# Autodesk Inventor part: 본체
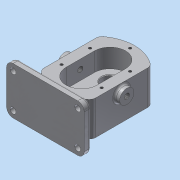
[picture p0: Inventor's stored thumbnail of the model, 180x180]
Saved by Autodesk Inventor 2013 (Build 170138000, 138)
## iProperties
Created: 2019-03
Part Number: 본체
Material: 알루미늄 6061
Document SubType Name: Modeling
Designer: dgall
Density: 2.71 g/cm^3
Mass: 1193.29 g
Surface Area: 723.767 cm^2
Volume: 440.327 cm^3
Author: dgall
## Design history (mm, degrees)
sketch "스케치2"
  geometry: L1 (-40, 44.721)-(-40, -44.721); L2 (40, 44.721)-(40, -44.721); A1 r 60 centre (0, 0) between (40, 44.721) and (-40, 44.721); A2 r 60 centre (0, 0) between (-40, -44.721) and (40, -44.721); 1 further point
  constraints: 4 end point, 4 point on circle, 2 centre point, 2 coincident, 1 horizontal alignment, 1 parallel, 1 vertical
  dimensions: "d7" = 60 radius of A1; "d8" = 60 radius of A2; "d9" = 80 distance between parallel lines of L2 L1
extrude "돌출2" new body sketch "스케치2" stored distance "d10" = 53; taper "d11" = 0 deg
sketch "스케치3"
  geometry: L1 (-24, 22)-(-24, -22); L2 (24, 22)-(24, -22); A1 r 60 centre (0, 0) between (40, 44.721) and (-40, 44.721) reference; A2 r 24 centre (0, 22) between (24, 22) and (-24, 22); A3 r 24 centre (0, -22) between (-24, -22) and (24, -22); 1 further point
  constraints: 4 end point, 4 point on circle, 4 tangent, 2 centre point, 2 vertical alignment, 1 equal radius, 1 horizontal alignment, 1 midpoint
  dimensions: "d13" = 44 distance of A3.centre A2.centre; "d14" = 24 radius of A2
extrude "돌출3" cut sketch "스케치3" distance "d15" = 29; taper "d16" = 0 deg
sketch "스케치4"
  geometry: A1 r 24 centre (0, 22) between (24, 22) and (-24, 22) reference; 2 further points
  constraints: 1 coincident
hole "구멍1" sketch "스케치4" at (0, 22) diameter "d17" = 17; stored, may be unused: countersink angle "d21" = 90 deg, drill point angle "d23" = 118 deg; dims "d18" = 6, "d19" = 25, "d20" = 15, "d22" = 8
sketch "스케치5"
  geometry: C1 r 12.5 at (0, -22); A1 r 24 centre (0, -22) between (-24, -22) and (24, -22) reference; 1 further point
  constraints: 1 centre point, 1 coincident
  dimensions: "d24" = 25 diameter of C1
extrude "돌출4" cut sketch "스케치5" distance "d25" = 15; taper "d26" = 0 deg
sketch "스케치6"
  geometry: C1 r 8.5 at (0, 22) reference; C2 r 19 at (0, 22)
  constraints: 1 centre point, 1 coincident
  dimensions: "d27" = 38 diameter of C2
extrude "돌출5" join sketch "스케치6" distance "d28" = 17; taper "d29" = 0 deg
sketch "스케치9"
  geometry: L1 (0, 0)-(0, 89.443) reference; L2 (70, 47.721)-(70, 85.721) reference; C1 r 11 at (14, 44.721); 2 further points
  constraints: 1 centre point, 1 midpoint
  dimensions: "d36" = 22 diameter of C1; "d37" = 22 vertical distance of point (70, 66.721) C1.centre; "d38" = 14 distance from line of L1 C1.centre
extrude "돌출6" join sketch "스케치9" distance "d39" = 8; taper "d40" = 0 deg
hole "구멍2" diameter "d43" = 8.376; stored, may be unused: countersink angle "d47" = 90 deg, drill point angle "d49" = 118 deg; dims "d41" = 10, "d42" = 10, "d44" = 6, "d45" = 25, "d46" = 15, "d48" = 8
node "작업 평면1"
sketch "스케치10"
  geometry: L1 (60, 46.5)-(-60, 46.5); L2 (-60, 46.5)-(-60, -26.5); L3 (-60, -26.5)-(60, -26.5); L4 (60, -26.5)-(60, 46.5); L5 (-19, -43.5)-(19, -43.5) reference; 2 further points
  constraints: 8 end point, 2 parallel, 1 horizontal, 1 midpoint, 1 perpendicular, 1 vertical alignment
  dimensions: "d51" = 73 distance of L3.end L1.start; "d53" = 120 distance of L2.end L3.end; "d54" = 90 distance between parallel lines of L5 L1
extrude "돌출7" join sketch "스케치10" distance "d55" = 10; taper "d56" = 0 deg
fillet "모깎기3" dims "d60" = 10
sketch "스케치12"
  geometry: L1 (50, 26.5)-(-50, 26.5) reference; L2 (60, 16.5)-(60, -36.5) reference; L3 (50, -46.5)-(-50, -46.5) reference; L4 (-60, -36.5)-(-60, 16.5) reference; L5 (-50, 26.5)-(50, 26.5) reference; L6 (60, 16.5)-(60, -36.5) reference; L7 (50, -46.5)-(-50, -46.5) reference; L8 (-60, -36.5)-(-60, 16.5) reference; L9 (-50, 26.5)-(50, 26.5) reference; L10 (60, 16.5)-(60, -36.5) reference; L11 (50, -46.5)-(-50, -46.5) reference; L12 (-60, -36.5)-(-60, 16.5) reference; L13 (-50, 26.5)-(50, 26.5) reference; L14 (-6, 26.5)-(-6, -16.5); L15 (-6, -16.5)-(6, -16.5); L16 (6, -16.5)-(6, 26.5); A1 r 10 centre (50, 16.5) between (60, 16.5) and (50, 26.5) reference; A2 r 10 centre (50, -36.5) between (50, -46.5) and (60, -36.5) reference; A3 r 10 centre (-50, -36.5) between (-60, -36.5) and (-50, -46.5) reference; A4 r 10 centre (-50, 16.5) between (-50, 26.5) and (-60, 16.5) reference; A5 r 10 centre (50, 16.5) between (60, 16.5) and (50, 26.5) reference; A6 r 10 centre (50, -36.5) between (50, -46.5) and (60, -36.5) reference; A7 r 10 centre (-50, -36.5) between (-60, -36.5) and (-50, -46.5) reference; A8 r 10 centre (-50, 16.5) between (-50, 26.5) and (-60, 16.5) reference; A9 r 10 centre (50, 16.5) between (60, 16.5) and (50, 26.5) reference; A10 r 10 centre (50, -36.5) between (50, -46.5) and (60, -36.5) reference; A11 r 10 centre (-50, -36.5) between (-60, -36.5) and (-50, -46.5) reference; A12 r 10 centre (-50, 16.5) between (-50, 26.5) and (-60, 16.5) reference; 3 further points
  constraints: 6 end point, 2 midpoint, 2 perpendicular, 2 point on line, 1 parallel, 1 vertical alignment
  dimensions: "d61" = 12 distance of L14.end L15.end; "d63" = 43 distance of L15.end L16.end
extrude "돌출9" join sketch "스케치12" stored distance "d64" = 12; taper "d65" = 0 deg
fillet "모깎기10" dims "d72" = 3
fillet "모깎기11" dims "d73" = 3
fillet "모깎기12" dims "d74" = 3
fillet "모깎기13" dims "d75" = 3
fillet "모깎기14" dims "d76" = 3
hole "구멍3" diameter "d79" = 9; stored, may be unused: countersink angle "d83" = 90 deg, drill point angle "d85" = 118 deg; dims "d77" = 10, "d78" = 10, "d80" = 6, "d81" = 25, "d82" = 15, "d84" = 8
sketch "스케치15"
  geometry: A1 r 24 centre (0, -22) between (-24, -22) and (24, -22) reference; A2 r 24 centre (0, 22) between (24, 22) and (-24, 22) reference; A3 r 60 centre (0, 0) between (40, 44.721) and (-40, 44.721) reference; 6 further points
  constraints: 4 horizontal alignment, 2 vertical alignment
  dimensions: "d112" = 106 distance of point (0, -53) point (0, 53); "d114" = 53 distance of A3.centre point (0, 53); "d115" = 31 distance of A2.centre point (-31, 22); "d116" = 31 distance of point (-31, -22) A1.centre; "d117" = 62 distance of point (31, 22) point (-31, 22); "d118" = 62 distance of point (-31, -22) point (31, -22)
hole "구멍6" sketch "스케치15" at (0, 53), (0, -53), (-31, 22), (31, 22), (31, -22), (-31, -22) diameter "d119" = 4.134; stored, may be unused: countersink angle "d123" = 90 deg, drill point angle "d125" = 118 deg; dims "d120" = 10, "d121" = 25, "d122" = 15, "d124" = 12
fillet "모깎기15" dims "d126" = 3
fillet "모깎기16" dims "d127" = 10
fillet "모깎기17" dims "d128" = 3
chamfer "모따기2" distance "d133" = 1; stored, may be unused: second distance "d134" = 2, angle "d135" = 45 deg
chamfer "모따기3" distance "d136" = 1; stored, may be unused: second distance "d137" = 2, angle "d138" = 45 deg
sketch "스케치16"
  geometry: L1 (-60, 16.5)-(-60, -36.5) reference; L2 (-50, -46.5)-(50, -46.5) reference; 2 further points
  constraints: 1 other
  dimensions: "d139" = 60 distance from line of L1 point (0, -36.5); "d140" = 10 distance from line of L2 point (0, -36.5)
feature "엠보싱1" sketch "스케치16" dims "d141" = 0.5, "d142" = 0
sketch "스케치17"
  geometry: C1 r 19 at (0, 0) reference; C2 r 8.5 at (0, 0); 1 further point
  constraints: 1 centre point, 1 coincident
  dimensions: "d144" = 17 diameter of C2
extrude "돌출10" cut sketch "스케치17" stored distance "d146" = 10; taper "d147" = 0 deg
sketch "스케치22"
  geometry: L1 (53, 13.258)-(55.067, 14.5) reference; L2 (55.067, 14.5)-(55.067, 26.5) reference; L3 (55.067, 26.5)-(60, 26.5) reference; L4 (60, 26.5)-(60, -26.5) reference; L5 (60, -26.5)-(44, -26.5) reference; L6 (41, -29.5)-(41, -43.5) reference; L7 (41, -43.5)-(30.5, -43.5) reference; L8 (30.5, -43.5)-(30.5, -17.5) reference; L9 (30.5, -17.5)-(34.5, -17.5) reference; L10 (34.5, -17.5)-(34.5, -3.5) reference; L11 (34.5, -3.5)-(35.5, -2.5) reference; L12 (35.5, -2.5)-(46, -2.5) reference; L13 (46, -2.5)-(46, 26.5) reference; L14 (46, 26.5)-(50.933, 26.5) reference; L15 (50.933, 26.5)-(50.933, 14.5) reference; L16 (50.933, 14.5)-(53, 13.258) reference; L17 (-60, 19.5)-(-60, 26.5) reference; L18 (-60, 26.5)-(-55.067, 26.5) reference; L19 (-55.067, 26.5)-(-55.067, 14.5) reference; L20 (-55.067, 14.5)-(-53, 13.258) reference; L21 (-53, 13.258)-(-50.933, 14.5) reference; L22 (-50.933, 14.5)-(-50.933, 26.5) reference; L23 (-50.933, 26.5)-(-46, 26.5) reference; L24 (-46, 26.5)-(-46, -2.5) reference; L25 (-46, -2.5)-(-35.5, -2.5) reference; L26 (-35.5, -2.5)-(-34.5, -3.5) reference; L27 (-34.5, -3.5)-(-34.5, -17.5) reference; L28 (-34.5, -17.5)-(-9.5, -17.5) reference; L29 (-9.5, -17.5)-(-9.5, -3.5) reference; L30 (-9.5, -3.5)-(-8.5, -2.5) reference; L31 (-8.5, -2.5)-(8.5, -2.5) reference; L32 (8.5, -2.5)-(9.5, -3.5) reference; L33 (9.5, -3.5)-(9.5, -17.5) reference; L34 (9.5, -17.5)-(13.5, -17.5) reference; L35 (13.5, -17.5)-(13.5, -43.5) reference; L36 (13.5, -43.5)-(3, -43.5) reference; L37 (3, -43.5)-(3, -29.5) reference; L38 (0, -26.5)-(-78, -26.5) reference; L39 (-78, -26.5)-(-78, 46.5) reference; L40 (-78, 46.5)-(-71, 46.5) reference; L41 (-68, 43.5)-(-68, 34.529) reference; L42 (-68, 34.529)-(-67.5, 34.529) reference; L43 (-67.5, 34.529)-(-67.5, 34.115) reference; L44 (-67.5, 34.115)-(-68, 34.115) reference; L45 (-68, 34.115)-(-68, 19.5) reference; L46 (-65, 16.5)-(-63, 16.5) reference; L47 (36, -42.8)-(36, -36.2); L48 (30.5, -17.5)-(13.5, -17.5); L49 (22, -17.5)-(22, -43.5); L50 (36, -36.2)-(22, -36.2); L51 (36, -42.8)-(36.421, -43.5); L52 (30.5, -43.5)-(13.5, -43.5) reference; L53 (36.421, -43.5)-(22, -43.5); A1 r 3 centre (44, -29.5) between (44, -26.5) and (41, -29.5) reference; A2 r 3 centre (-63, 19.5) between (-63, 16.5) and (-60, 19.5) reference; A3 r 3 centre (0, -29.5) between (3, -29.5) and (0, -26.5) reference; A4 r 3 centre (-71, 43.5) between (-68, 43.5) and (-71, 46.5) reference; A5 r 3 centre (-65, 19.5) between (-68, 19.5) and (-65, 16.5) reference; 1 further point
  constraints: 12 end point, 3 perpendicular, 2 point on line, 1 collinear, 1 midpoint, 1 parallel, 1 vertical
  dimensions: "d161" = 28 diameter of L47 L49; "d162" = 0.7 vertical distance of L51.end L47.start; "d163" = 7.3 vertical distance of L47.end L51.end
revolve "회전3" sketch "스케치22" stored, may be unused: angle "d164" = 90 deg
node "솔리드2"
mirror "대칭1"
pattern_linear "직사각형 패턴1" dims "d88" = 100, "d91" = 53
node "절단 모서리 투영3"
node "절단 모서리 투영4"
node "절단 모서리 투영5"
node "절단 모서리 투영9"
other parameters: "d12" = 24, "d50" = -78
